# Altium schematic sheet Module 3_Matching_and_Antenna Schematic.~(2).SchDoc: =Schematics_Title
size A4; PageSetup: Record=PageOptions¦CenterHorizontal=True¦CenterVertical=True¦PrintScale=0.97¦XCorrection=1.00¦YCorrection=1.00¦PrintKind=0¦BorderSize=5000000¦LeftOffset=0¦BottomOffset=0¦Orientation=2¦PaperLength=1000¦PaperWidth=1000¦Scale=100¦PaperSource=7¦PrintQuality=-4¦MediaType=1¦DitherType=10¦PaperKind=A4¦PrintScaleMode=1; SheetNumber: 5; SheetTotal: 5
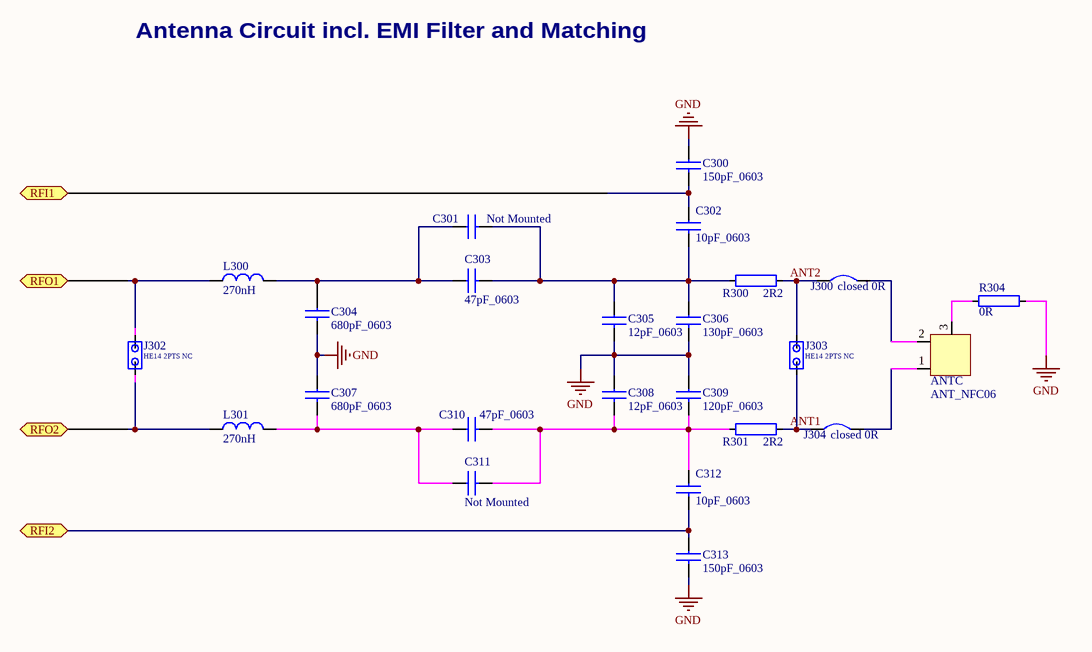
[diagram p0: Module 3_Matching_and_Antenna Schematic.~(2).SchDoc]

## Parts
ANTC  ANT_NFC06  [ANT_NFC08]  (net tie, no BOM)
C300  150pF_0603  [C0603]
C301  Not Mounted  [C0603]
C302  10pF_0603  [C0603]
C303  47pF_0603  [C0603]
C304  680pF_0603  [C0603]
C305  12pF_0603  [C0603]
C306  130pF_0603  [C0603]
C307  680pF_0603  [C0603]
C308  12pF_0603  [C0603]
C309  120pF_0603  [C0603]
C310  47pF_0603  [C0603]
C311  Not Mounted  [C0603]
C312  10pF_0603  [C0603]
C313  150pF_0603  [C0603]
J300  closed 0R  [JP2_SMD_closed_0402]  (net tie)
J302  HE14 2PTS NC  [HE14-1x2-DROIT-sans-3D-largeur-1.8]
J303  HE14 2PTS NC  [HE14-1x2-DROIT-sans-3D-largeur-1.8]
J304  closed 0R  [JP2_SMD_closed_0402]  (net tie)
L300  270nH  [L0603]
L301  270nH  [L0603]
R300  2R2  [R0603]
R301  2R2  [R0603]
R304  0R  [R0603]

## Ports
RFI1 (bidir), RFI2 (bidir), RFO1 (bidir), RFO2 (bidir)

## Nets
GND: C300.1 C304.2 C305.2 C306.2 C307.1 C308.1 C309.1 C313.2 R304.1
ANT1: J303.2 J304.1 R301.1
ANT2: J300.1 J303.1 R300.1
RFI1: C300.2 C302.1 ; port RFI1
RFI2: C312.2 C313.1 ; port RFI2
RFO1: J302.1 L300.2 ; port RFO1
RFO2: J302.2 L301.2 ; port RFO2
NetANTC_1: ANTC.1 J304.2
NetANTC_2: ANTC.2 J300.2
NetANTC_3: ANTC.3 R304.2
NetC301_1: C301.1 C303.1 C304.1 L300.1
NetC301_2: C301.2 C302.2 C303.2 C305.1 C306.1 R300.2
NetC307_2: C307.2 C310.1 C311.1 L301.1
NetC308_2: C308.2 C309.2 C310.2 C311.2 C312.1 R301.2

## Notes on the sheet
- Antenna Circuit incl. EMI Filter and Matching

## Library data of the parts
ANTC = ANT_NFC06: PickPlace: No
C300 C313 = C_150p_0603: 150p_COG 0603; Manufacturer: MURATA; Manufacturer Part Number: GRM1885C1H151GA01D; PickPlace: Yes
C301 C311 = C_12p_0603: Manufacturer: MULTI-SOURCES; PickPlace: Yes
C302 C312 = C_10p_0603: 10p_COG; Manufacturer: MULTICOMP; Manufacturer Part Number: MC0603N100F500CT; PickPlace: Yes
C303 = C_82p_0603: 47p_COG; Manufacturer: MURATA; Manufacturer Part Number: GCM1555C1H47FA16D; 2nd Source: 82pF ±1% 50V  C0G, NP0 0603; PickPlace: Yes
C304 C307 = C_680p_0603: 680p_COG; Manufacturer: MURATA; Manufacturer Part Number: GRM1885C1H681GA01D; 2nd Source: 680pF ±2% 50V  C0G, NP0 0603; PickPlace: Yes
C305 C308 = C_5p6_0603: 12pF_COG 0603; Manufacturer: MURATA; Manufacturer Part Number: GRM1555C1H120GA01D; PickPlace: Yes
C306 = C_120p_0603: 130pF_COG; Manufacturer: MURATA; Manufacturer Part Number: GCM1555C1H131FA16D; 2nd Source: 130pF ±1% 50V  C0G, NP0 0603; PickPlace: Yes
C309 = C_120p_0603: 120pF_COG; Manufacturer: MURATA; Manufacturer Part Number: GCM1555C1H131FA16D; 2nd Source: 130pF ±1% 50V  C0G, NP0 0603; PickPlace: Yes
C310 = C_82p_0603: 47p_COG; Manufacturer: MURATA; Manufacturer Part Number: GCM1555C1H47FA16D; 2nd Source: 47pF ±1% 50V  C0G, NP0 0603; PickPlace: Yes
J300 J304 = solder_jumper_closed_0402: 0R 0402; Manufacturer: MULTI-SOURCES; Manufacturer Part Number: RESISTOR 0402 0R 62mW; PickPlace: Yes
J302 J303 = HE14-1X2-MALE-DROIT-NC-special: CONN HE14 2PTS MALE VERTICAL NOT FITTED; Manufacturer: MULTI-SOURCES; 2nd Source: doublesourcing allowed; PickPlace: No
L300 L301 = 0603LS-271XGLB: 0603LS-271XGRC; Manufacturer: COILCRAFT; PickPlace: Yes
R300 R301 = R0603_2R2: 2R2, 0603; Manufacturer: MULTI-SOURCES; Manufacturer Part Number: RESISTOR 0603 2.2 Ohms 1%; PickPlace: Yes
R304 = R0603_0R: 0R, 0603; Manufacturer: MULTI-SOURCES; Manufacturer Part Number: RESISTOR 0603 0R 62mW; PickPlace: Yes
